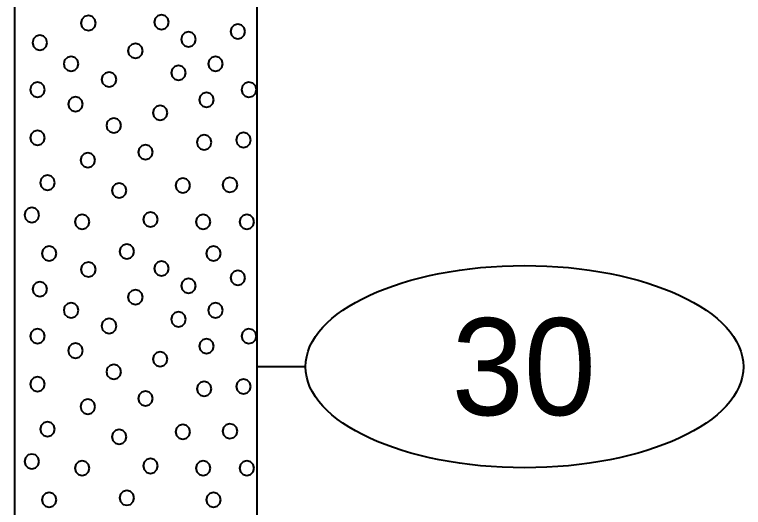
# Model space of a CAD drawing. Extents: x -76 to 974, y -1080 to -735.
# Drawn here: x 15.1 to 22.61, y -829.67 to -824.59 of the extents above; entities that cross this region are included whole.
import ezdxf
from ezdxf.enums import TextEntityAlignment as Align

# ---------------------------------------------------------------- set-up
doc = ezdxf.new("R2010")
doc.units = 0
doc.header["$LTSCALE"] = 0.36
doc.layers.add('27', color=7, linetype='Continuous', lineweight=40)

msp = doc.modelspace()

# ---------------------------------------------------------------- linework, layer by layer
at = {"layer": '27'}
for p, q in [((15.0967, -819.2173), (15.0967, -838.7173)), ((17.5967, -838.7173), (17.5967, -819.2173)), ((18.0967, -828.2173), (17.5967, -828.2173))]:
    msp.add_line(p, q, dxfattribs=at)
for points in [[(16.6886, -824.6662), (16.6784, -824.6281), (16.6505, -824.6002), (16.6124, -824.59), (16.5743, -824.6002), (16.5464, -824.6281), (16.5362, -824.6662), (16.5464, -824.7043), (16.5743, -824.7322), (16.6124, -824.7424), (16.6505, -824.7322), (16.6784, -824.7043)], [(15.9335, -824.6752), (15.9233, -824.6371), (15.8954, -824.6092), (15.8573, -824.599), (15.8192, -824.6092), (15.7913, -824.6371), (15.7811, -824.6752), (15.7913, -824.7133), (15.8192, -824.7412), (15.8573, -824.7514), (15.8954, -824.7412), (15.9233, -824.7133)], [(17.4741, -824.7621), (17.4639, -824.724), (17.436, -824.6961), (17.3979, -824.6859), (17.3598, -824.6961), (17.3319, -824.724), (17.3217, -824.7621), (17.3319, -824.8002), (17.3598, -824.8281), (17.3979, -824.8383), (17.436, -824.8281), (17.4639, -824.8002)], [(15.4324, -824.8778), (15.4222, -824.8397), (15.3943, -824.8118), (15.3562, -824.8016), (15.3181, -824.8118), (15.2902, -824.8397), (15.28, -824.8778), (15.2902, -824.9159), (15.3181, -824.9438), (15.3562, -824.954), (15.3943, -824.9438), (15.4222, -824.9159)], [(16.9668, -824.8434), (16.9566, -824.8053), (16.9287, -824.7774), (16.8906, -824.7672), (16.8525, -824.7774), (16.8246, -824.8053), (16.8144, -824.8434), (16.8246, -824.8815), (16.8525, -824.9094), (16.8906, -824.9196), (16.9287, -824.9094), (16.9566, -824.8815)], [(16.4185, -824.961), (16.4083, -824.9229), (16.3804, -824.895), (16.3423, -824.8848), (16.3042, -824.895), (16.2763, -824.9229), (16.2661, -824.961), (16.2763, -824.9991), (16.3042, -825.027), (16.3423, -825.0372), (16.3804, -825.027), (16.4083, -824.9991)], [(15.7553, -825.0964), (15.7451, -825.0583), (15.7172, -825.0304), (15.6791, -825.0202), (15.641, -825.0304), (15.6131, -825.0583), (15.6029, -825.0964), (15.6131, -825.1345), (15.641, -825.1624), (15.6791, -825.1726), (15.7172, -825.1624), (15.7451, -825.1345)], [(17.244, -825.0964), (17.2338, -825.0583), (17.2059, -825.0304), (17.1678, -825.0202), (17.1297, -825.0304), (17.1018, -825.0583), (17.0916, -825.0964), (17.1018, -825.1345), (17.1297, -825.1624), (17.1678, -825.1726), (17.2059, -825.1624), (17.2338, -825.1345)], [(16.8626, -825.1892), (16.8524, -825.1511), (16.8245, -825.1232), (16.7864, -825.113), (16.7483, -825.1232), (16.7204, -825.1511), (16.7102, -825.1892), (16.7204, -825.2273), (16.7483, -825.2552), (16.7864, -825.2654), (16.8245, -825.2552), (16.8524, -825.2273)], [(16.1469, -825.2579), (16.1367, -825.2198), (16.1088, -825.1919), (16.0707, -825.1817), (16.0326, -825.1919), (16.0047, -825.2198), (15.9945, -825.2579), (16.0047, -825.296), (16.0326, -825.3239), (16.0707, -825.3341), (16.1088, -825.3239), (16.1367, -825.296)], [(15.4095, -825.3621), (15.3993, -825.324), (15.3714, -825.2961), (15.3333, -825.2859), (15.2952, -825.2961), (15.2673, -825.324), (15.2571, -825.3621), (15.2673, -825.4002), (15.2952, -825.4281), (15.3333, -825.4383), (15.3714, -825.4281), (15.3993, -825.4002)], [(17.5898, -825.3621), (17.5795, -825.324), (17.5517, -825.2961), (17.5136, -825.2859), (17.4755, -825.2961), (17.4476, -825.324), (17.4374, -825.3621), (17.4476, -825.4002), (17.4755, -825.4281), (17.5136, -825.4383), (17.5517, -825.4281), (17.5795, -825.4002)], [(17.1512, -825.4664), (17.141, -825.4283), (17.1131, -825.4004), (17.075, -825.3902), (17.0369, -825.4004), (17.009, -825.4283), (16.9988, -825.4664), (17.009, -825.5045), (17.0369, -825.5324), (17.075, -825.5426), (17.1131, -825.5324), (17.141, -825.5045)], [(15.8011, -825.5121), (15.7909, -825.474), (15.763, -825.4461), (15.7249, -825.4359), (15.6868, -825.4461), (15.6589, -825.474), (15.6487, -825.5121), (15.6589, -825.5502), (15.6868, -825.5781), (15.7249, -825.5883), (15.763, -825.5781), (15.7909, -825.5502)], [(16.6732, -825.5998), (16.663, -825.5617), (16.6351, -825.5339), (16.597, -825.5236), (16.5589, -825.5339), (16.531, -825.5617), (16.5208, -825.5998), (16.531, -825.6379), (16.5589, -825.6658), (16.597, -825.676), (16.6351, -825.6658), (16.663, -825.6379)], [(16.1952, -825.7308), (16.185, -825.6927), (16.1571, -825.6648), (16.119, -825.6546), (16.0809, -825.6648), (16.053, -825.6927), (16.0428, -825.7308), (16.053, -825.7689), (16.0809, -825.7968), (16.119, -825.807), (16.1571, -825.7968), (16.185, -825.7689)], [(15.4095, -825.8579), (15.3993, -825.8198), (15.3714, -825.7919), (15.3333, -825.7817), (15.2952, -825.7919), (15.2673, -825.8198), (15.2571, -825.8579), (15.2673, -825.896), (15.2952, -825.9239), (15.3333, -825.9341), (15.3714, -825.9239), (15.3993, -825.896)], [(17.1283, -825.9049), (17.1181, -825.8668), (17.0902, -825.839), (17.0521, -825.8287), (17.014, -825.839), (16.9861, -825.8668), (16.9759, -825.9049), (16.9861, -825.943), (17.014, -825.9709), (17.0521, -825.9811), (17.0902, -825.9709), (17.1181, -825.943)], [(17.5325, -825.8808), (17.5223, -825.8427), (17.4944, -825.8148), (17.4563, -825.8046), (17.4182, -825.8148), (17.3904, -825.8427), (17.3801, -825.8808), (17.3904, -825.9189), (17.4182, -825.9468), (17.4563, -825.957), (17.4944, -825.9468), (17.5223, -825.9189)], [(16.5232, -826.0054), (16.5129, -825.9673), (16.4851, -825.9394), (16.447, -825.9292), (16.4089, -825.9394), (16.381, -825.9673), (16.3708, -826.0054), (16.381, -826.0435), (16.4089, -826.0714), (16.447, -826.0816), (16.4851, -826.0714), (16.5129, -826.0435)], [(15.9282, -826.0893), (15.918, -826.0512), (15.8901, -826.0233), (15.852, -826.0131), (15.8139, -826.0233), (15.786, -826.0512), (15.7758, -826.0893), (15.786, -826.1274), (15.8139, -826.1553), (15.852, -826.1655), (15.8901, -826.1553), (15.918, -826.1274)], [(15.5125, -826.3207), (15.5023, -826.2826), (15.4744, -826.2547), (15.4363, -826.2445), (15.3982, -826.2547), (15.3703, -826.2826), (15.3601, -826.3207), (15.3703, -826.3588), (15.3982, -826.3866), (15.4363, -826.3969), (15.4744, -826.3866), (15.5023, -826.3588)], [(16.9084, -826.3499), (16.8981, -826.3118), (16.8703, -826.2839), (16.8322, -826.2737), (16.7941, -826.2839), (16.7662, -826.3118), (16.756, -826.3499), (16.7662, -826.388), (16.7941, -826.4159), (16.8322, -826.4261), (16.8703, -826.4159), (16.8981, -826.388)], [(17.394, -826.3423), (17.3838, -826.3042), (17.3559, -826.2763), (17.3178, -826.2661), (17.2797, -826.2763), (17.2518, -826.3042), (17.2416, -826.3423), (17.2518, -826.3804), (17.2797, -826.4083), (17.3178, -826.4185), (17.3559, -826.4083), (17.3838, -826.3804)], [(16.2511, -826.4007), (16.2409, -826.3626), (16.213, -826.3348), (16.1749, -826.3245), (16.1368, -826.3348), (16.1089, -826.3626), (16.0987, -826.4007), (16.1089, -826.4388), (16.1368, -826.4667), (16.1749, -826.4769), (16.213, -826.4667), (16.2409, -826.4388)], [(15.351, -826.6537), (15.3408, -826.6156), (15.3129, -826.5877), (15.2748, -826.5775), (15.2367, -826.5877), (15.2089, -826.6156), (15.1986, -826.6537), (15.2089, -826.6918), (15.2367, -826.7197), (15.2748, -826.7299), (15.3129, -826.7197), (15.3408, -826.6918)], [(15.8697, -826.7236), (15.8595, -826.6855), (15.8316, -826.6577), (15.7935, -826.6474), (15.7554, -826.6577), (15.7275, -826.6855), (15.7173, -826.7236), (15.7275, -826.7617), (15.7554, -826.7896), (15.7935, -826.7998), (15.8316, -826.7896), (15.8595, -826.7617)], [(16.574, -826.7008), (16.5638, -826.6627), (16.5359, -826.6348), (16.4978, -826.6246), (16.4597, -826.6348), (16.4318, -826.6627), (16.4216, -826.7008), (16.4318, -826.7389), (16.4597, -826.7668), (16.4978, -826.777), (16.5359, -826.7668), (16.5638, -826.7389)], [(17.1168, -826.7236), (17.1066, -826.6855), (17.0787, -826.6577), (17.0406, -826.6474), (17.0025, -826.6577), (16.9746, -826.6855), (16.9644, -826.7236), (16.9746, -826.7617), (17.0025, -826.7896), (17.0406, -826.7998), (17.0787, -826.7896), (17.1066, -826.7617)], [(17.5669, -826.7236), (17.5567, -826.6855), (17.5288, -826.6577), (17.4907, -826.6474), (17.4526, -826.6577), (17.4247, -826.6855), (17.4145, -826.7236), (17.4247, -826.7617), (17.4526, -826.7896), (17.4907, -826.7998), (17.5288, -826.7896), (17.5567, -826.7617)], [(15.5286, -827.0499), (15.5184, -827.0118), (15.4905, -826.9839), (15.4524, -826.9737), (15.4143, -826.9839), (15.3864, -827.0118), (15.3762, -827.0499), (15.3864, -827.088), (15.4143, -827.1159), (15.4524, -827.1261), (15.4905, -827.1159), (15.5184, -827.088)], [(16.3296, -827.0303), (16.3193, -826.9922), (16.2915, -826.9643), (16.2534, -826.9541), (16.2153, -826.9643), (16.1874, -826.9922), (16.1772, -827.0303), (16.1874, -827.0684), (16.2153, -827.0963), (16.2534, -827.1065), (16.2915, -827.0963), (16.3193, -827.0684)], [(17.2232, -827.05), (17.213, -827.0119), (17.1851, -826.984), (17.147, -826.9738), (17.1089, -826.984), (17.081, -827.0119), (17.0708, -827.05), (17.081, -827.0881), (17.1089, -827.116), (17.147, -827.1262), (17.1851, -827.116), (17.213, -827.0881)], [(15.9335, -827.2152), (15.9233, -827.1771), (15.8954, -827.1492), (15.8573, -827.139), (15.8192, -827.1492), (15.7913, -827.1771), (15.7811, -827.2152), (15.7913, -827.2533), (15.8192, -827.2812), (15.8573, -827.2914), (15.8954, -827.2812), (15.9233, -827.2533)], [(16.6886, -827.2062), (16.6784, -827.1681), (16.6505, -827.1402), (16.6124, -827.13), (16.5743, -827.1402), (16.5464, -827.1681), (16.5362, -827.2062), (16.5464, -827.2443), (16.5743, -827.2722), (16.6124, -827.2824), (16.6505, -827.2722), (16.6784, -827.2443)], [(17.4741, -827.3021), (17.4639, -827.264), (17.436, -827.2361), (17.3979, -827.2259), (17.3598, -827.2361), (17.3319, -827.264), (17.3217, -827.3021), (17.3319, -827.3402), (17.3598, -827.3681), (17.3979, -827.3783), (17.436, -827.3681), (17.4639, -827.3402)], [(15.4324, -827.4178), (15.4222, -827.3797), (15.3943, -827.3518), (15.3562, -827.3416), (15.3181, -827.3518), (15.2902, -827.3797), (15.28, -827.4178), (15.2902, -827.4559), (15.3181, -827.4838), (15.3562, -827.494), (15.3943, -827.4838), (15.4222, -827.4559)], [(16.9668, -827.3834), (16.9566, -827.3453), (16.9287, -827.3174), (16.8906, -827.3072), (16.8525, -827.3174), (16.8246, -827.3453), (16.8144, -827.3834), (16.8246, -827.4215), (16.8525, -827.4494), (16.8906, -827.4596), (16.9287, -827.4494), (16.9566, -827.4215)], [(16.4185, -827.501), (16.4083, -827.4629), (16.3804, -827.435), (16.3423, -827.4248), (16.3042, -827.435), (16.2763, -827.4629), (16.2661, -827.501), (16.2763, -827.5391), (16.3042, -827.567), (16.3423, -827.5772), (16.3804, -827.567), (16.4083, -827.5391)], [(15.7553, -827.6364), (15.7451, -827.5983), (15.7172, -827.5704), (15.6791, -827.5602), (15.641, -827.5704), (15.6131, -827.5983), (15.6029, -827.6364), (15.6131, -827.6745), (15.641, -827.7024), (15.6791, -827.7126), (15.7172, -827.7024), (15.7451, -827.6745)], [(17.244, -827.6364), (17.2338, -827.5983), (17.2059, -827.5704), (17.1678, -827.5602), (17.1297, -827.5704), (17.1018, -827.5983), (17.0916, -827.6364), (17.1018, -827.6745), (17.1297, -827.7024), (17.1678, -827.7126), (17.2059, -827.7024), (17.2338, -827.6745)], [(16.8626, -827.7292), (16.8524, -827.6911), (16.8245, -827.6632), (16.7864, -827.653), (16.7483, -827.6632), (16.7204, -827.6911), (16.7102, -827.7292), (16.7204, -827.7673), (16.7483, -827.7952), (16.7864, -827.8054), (16.8245, -827.7952), (16.8524, -827.7673)], [(16.1469, -827.7979), (16.1367, -827.7598), (16.1088, -827.7319), (16.0707, -827.7217), (16.0326, -827.7319), (16.0047, -827.7598), (15.9945, -827.7979), (16.0047, -827.836), (16.0326, -827.8639), (16.0707, -827.8741), (16.1088, -827.8639), (16.1367, -827.836)], [(15.4095, -827.9021), (15.3993, -827.864), (15.3714, -827.8361), (15.3333, -827.8259), (15.2952, -827.8361), (15.2673, -827.864), (15.2571, -827.9021), (15.2673, -827.9402), (15.2952, -827.9681), (15.3333, -827.9783), (15.3714, -827.9681), (15.3993, -827.9402)], [(17.5898, -827.9021), (17.5795, -827.864), (17.5517, -827.8361), (17.5136, -827.8259), (17.4755, -827.8361), (17.4476, -827.864), (17.4374, -827.9021), (17.4476, -827.9402), (17.4755, -827.9681), (17.5136, -827.9783), (17.5517, -827.9681), (17.5795, -827.9402)], [(15.8011, -828.0521), (15.7909, -828.014), (15.763, -827.9861), (15.7249, -827.9759), (15.6868, -827.9861), (15.6589, -828.014), (15.6487, -828.0521), (15.6589, -828.0902), (15.6868, -828.1181), (15.7249, -828.1283), (15.763, -828.1181), (15.7909, -828.0902)], [(17.1512, -828.0064), (17.141, -827.9683), (17.1131, -827.9404), (17.075, -827.9302), (17.0369, -827.9404), (17.009, -827.9683), (16.9988, -828.0064), (17.009, -828.0445), (17.0369, -828.0724), (17.075, -828.0826), (17.1131, -828.0724), (17.141, -828.0445)], [(16.6732, -828.1398), (16.663, -828.1017), (16.6351, -828.0739), (16.597, -828.0636), (16.5589, -828.0739), (16.531, -828.1017), (16.5208, -828.1398), (16.531, -828.1779), (16.5589, -828.2058), (16.597, -828.216), (16.6351, -828.2058), (16.663, -828.1779)], [(16.1952, -828.2708), (16.185, -828.2327), (16.1571, -828.2048), (16.119, -828.1946), (16.0809, -828.2048), (16.053, -828.2327), (16.0428, -828.2708), (16.053, -828.3089), (16.0809, -828.3368), (16.119, -828.347), (16.1571, -828.3368), (16.185, -828.3089)], [(15.4095, -828.3979), (15.3993, -828.3598), (15.3714, -828.3319), (15.3333, -828.3217), (15.2952, -828.3319), (15.2673, -828.3598), (15.2571, -828.3979), (15.2673, -828.436), (15.2952, -828.4639), (15.3333, -828.4741), (15.3714, -828.4639), (15.3993, -828.436)], [(17.5325, -828.4208), (17.5223, -828.3827), (17.4944, -828.3548), (17.4563, -828.3446), (17.4182, -828.3548), (17.3904, -828.3827), (17.3801, -828.4208), (17.3904, -828.4589), (17.4182, -828.4868), (17.4563, -828.497), (17.4944, -828.4868), (17.5223, -828.4589)], [(17.1283, -828.4449), (17.1181, -828.4068), (17.0902, -828.379), (17.0521, -828.3687), (17.014, -828.379), (16.9861, -828.4068), (16.9759, -828.4449), (16.9861, -828.483), (17.014, -828.5109), (17.0521, -828.5211), (17.0902, -828.5109), (17.1181, -828.483)], [(16.5232, -828.5454), (16.5129, -828.5073), (16.4851, -828.4794), (16.447, -828.4692), (16.4089, -828.4794), (16.381, -828.5073), (16.3708, -828.5454), (16.381, -828.5835), (16.4089, -828.6114), (16.447, -828.6216), (16.4851, -828.6114), (16.5129, -828.5835)], [(15.9282, -828.6293), (15.918, -828.5912), (15.8901, -828.5633), (15.852, -828.5531), (15.8139, -828.5633), (15.786, -828.5912), (15.7758, -828.6293), (15.786, -828.6674), (15.8139, -828.6953), (15.852, -828.7055), (15.8901, -828.6953), (15.918, -828.6674)], [(15.5125, -828.8607), (15.5023, -828.8226), (15.4744, -828.7947), (15.4363, -828.7845), (15.3982, -828.7947), (15.3703, -828.8226), (15.3601, -828.8607), (15.3703, -828.8988), (15.3982, -828.9266), (15.4363, -828.9369), (15.4744, -828.9266), (15.5023, -828.8988)], [(16.2511, -828.9407), (16.2409, -828.9026), (16.213, -828.8748), (16.1749, -828.8645), (16.1368, -828.8748), (16.1089, -828.9026), (16.0987, -828.9407), (16.1089, -828.9788), (16.1368, -829.0067), (16.1749, -829.0169), (16.213, -829.0067), (16.2409, -828.9788)], [(16.9084, -828.8899), (16.8981, -828.8518), (16.8703, -828.8239), (16.8322, -828.8137), (16.7941, -828.8239), (16.7662, -828.8518), (16.756, -828.8899), (16.7662, -828.928), (16.7941, -828.9559), (16.8322, -828.9661), (16.8703, -828.9559), (16.8981, -828.928)], [(17.394, -828.8823), (17.3838, -828.8442), (17.3559, -828.8163), (17.3178, -828.8061), (17.2797, -828.8163), (17.2518, -828.8442), (17.2416, -828.8823), (17.2518, -828.9204), (17.2797, -828.9483), (17.3178, -828.9585), (17.3559, -828.9483), (17.3838, -828.9204)], [(15.351, -829.1937), (15.3408, -829.1556), (15.3129, -829.1277), (15.2748, -829.1175), (15.2367, -829.1277), (15.2089, -829.1556), (15.1986, -829.1937), (15.2089, -829.2318), (15.2367, -829.2597), (15.2748, -829.2699), (15.3129, -829.2597), (15.3408, -829.2318)], [(16.574, -829.2408), (16.5638, -829.2027), (16.5359, -829.1748), (16.4978, -829.1646), (16.4597, -829.1748), (16.4318, -829.2027), (16.4216, -829.2408), (16.4318, -829.2789), (16.4597, -829.3068), (16.4978, -829.317), (16.5359, -829.3068), (16.5638, -829.2789)], [(15.8697, -829.2636), (15.8595, -829.2255), (15.8316, -829.1977), (15.7935, -829.1874), (15.7554, -829.1977), (15.7275, -829.2255), (15.7173, -829.2636), (15.7275, -829.3017), (15.7554, -829.3296), (15.7935, -829.3398), (15.8316, -829.3296), (15.8595, -829.3017)], [(17.1168, -829.2636), (17.1066, -829.2255), (17.0787, -829.1977), (17.0406, -829.1874), (17.0025, -829.1977), (16.9746, -829.2255), (16.9644, -829.2636), (16.9746, -829.3017), (17.0025, -829.3296), (17.0406, -829.3398), (17.0787, -829.3296), (17.1066, -829.3017)], [(17.5669, -829.2636), (17.5567, -829.2255), (17.5288, -829.1977), (17.4907, -829.1874), (17.4526, -829.1977), (17.4247, -829.2255), (17.4145, -829.2636), (17.4247, -829.3017), (17.4526, -829.3296), (17.4907, -829.3398), (17.5288, -829.3296), (17.5567, -829.3017)], [(15.5286, -829.5899), (15.5184, -829.5518), (15.4905, -829.5239), (15.4524, -829.5137), (15.4143, -829.5239), (15.3864, -829.5518), (15.3762, -829.5899), (15.3864, -829.628), (15.4143, -829.6559), (15.4524, -829.6661), (15.4905, -829.6559), (15.5184, -829.628)], [(16.3296, -829.5703), (16.3193, -829.5322), (16.2915, -829.5043), (16.2534, -829.4941), (16.2153, -829.5043), (16.1874, -829.5322), (16.1772, -829.5703), (16.1874, -829.6084), (16.2153, -829.6363), (16.2534, -829.6465), (16.2915, -829.6363), (16.3193, -829.6084)], [(17.2232, -829.59), (17.213, -829.5519), (17.1851, -829.524), (17.147, -829.5138), (17.1089, -829.524), (17.081, -829.5519), (17.0708, -829.59), (17.081, -829.6281), (17.1089, -829.656), (17.147, -829.6662), (17.1851, -829.656), (17.213, -829.6281)]]:
    msp.add_lwpolyline(points, close=True, dxfattribs=at)
msp.add_ellipse((20.3541, -828.2173), major_axis=(2.2574, 0), ratio=0.461538, dxfattribs=at)

# ---------------------------------------------------------------- texts
msp.add_text('30', height=1, dxfattribs=at).set_placement((20.3469, -828.7172), align=Align.CENTER)

doc.saveas('drawing.dxf')
